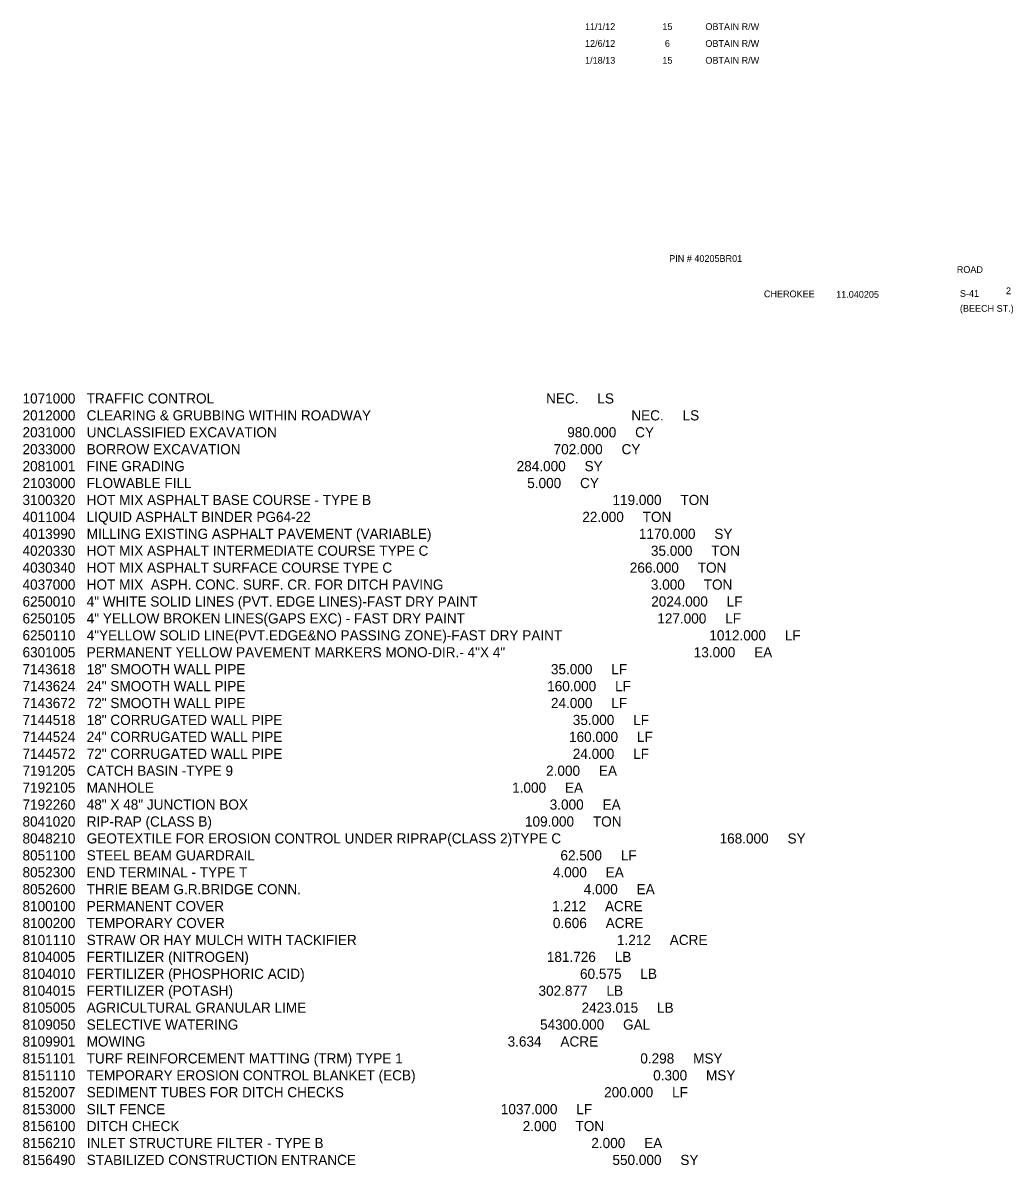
# Model space of a CAD drawing. Extents: x 160093 to 164626, y 177093 to 182727.
# Drawn here: x 163824 to 164555, y 178608 to 179452 of the extents above; entities that cross this region are included whole.
import ezdxf

# ---------------------------------------------------------------- set-up
doc = ezdxf.new("R2010")
doc.units = 0
for name, color, linetype in [('Default', 7, 'Continuous'), ('Level 37', 7, 'Continuous'), ('RD_SHT_TX', 7, 'Continuous')]:
    doc.layers.add(name, color=color, linetype=linetype)

msp = doc.modelspace()

# ---------------------------------------------------------------- texts
at = {"layer": 'Default'}
for s, height, p in [('ROAD', 5, (164513.57, 179266.9)), ('11.040205', 5, (164424.45, 179248.56)), ('S-41', 5, (164515.88, 179249.23)), ('(BEECH ST.)', 5, (164515.88, 179238.22)), ('1071000   TRAFFIC CONTROL                                                                                        NEC.     LS', 7.5, (163823.36, 179170.47)), ('2012000   CLEARING & GRUBBING WITHIN ROADWAY                                                                     NEC.     LS', 7.5, (163823.36, 179157.97)), ('2031000   UNCLASSIFIED EXCAVATION                                                                             980.000     CY', 7.5, (163823.36, 179145.47)), ('2033000   BORROW EXCAVATION                                                                                   702.000     CY', 7.5, (163823.36, 179132.97)), ('2081001   FINE GRADING                                                                                        284.000     SY', 7.5, (163823.36, 179120.47)), ('2103000   FLOWABLE FILL                                                                                         5.000     CY', 7.5, (163823.36, 179107.97)), ('3100320   HOT MIX ASPHALT BASE COURSE - TYPE B                                                                119.000     TON', 7.5, (163823.36, 179095.47)), ('4011004   LIQUID ASPHALT BINDER PG64-22                                                                        22.000     TON', 7.5, (163823.36, 179082.97)), ('4013990   MILLING EXISTING ASPHALT PAVEMENT (VARIABLE)                                                       1170.000     SY', 7.5, (163823.36, 179070.47)), ('4020330   HOT MIX ASPHALT INTERMEDIATE COURSE TYPE C                                                           35.000     TON', 7.5, (163823.36, 179057.97)), ('4030340   HOT MIX ASPHALT SURFACE COURSE TYPE C                                                               266.000     TON', 7.5, (163823.36, 179045.47)), ('4037000   HOT MIX  ASPH. CONC. SURF. CR. FOR DITCH PAVING                                                       3.000     TON', 7.5, (163823.36, 179032.97)), ('6250010   4" WHITE SOLID LINES (PVT. EDGE LINES)-FAST DRY PAINT                                              2024.000     LF', 7.5, (163823.36, 179020.47)), ('6250105   4" YELLOW BROKEN LINES(GAPS EXC) - FAST DRY PAINT                                                   127.000     LF', 7.5, (163823.36, 179007.97)), ('6250110   4"YELLOW SOLID LINE(PVT.EDGE&NO PASSING ZONE)-FAST DRY PAINT                                       1012.000     LF', 7.5, (163823.36, 178995.47)), ('6301005   PERMANENT YELLOW PAVEMENT MARKERS MONO-DIR.- 4"X 4"                                                  13.000     EA', 7.5, (163823.36, 178982.97)), ('7143618   18" SMOOTH WALL PIPE                                                                                 35.000     LF', 7.5, (163823.36, 178970.47)), ('7143624   24" SMOOTH WALL PIPE                                                                                160.000     LF', 7.5, (163823.36, 178957.97)), ('7143672   72" SMOOTH WALL PIPE                                                                                 24.000     LF', 7.5, (163823.36, 178945.47)), ('7144518   18" CORRUGATED WALL PIPE                                                                             35.000     LF', 7.5, (163823.36, 178932.97)), ('7144524   24" CORRUGATED WALL PIPE                                                                            160.000     LF', 7.5, (163823.36, 178920.47)), ('7144572   72" CORRUGATED WALL PIPE                                                                             24.000     LF', 7.5, (163823.36, 178907.97)), ('7191205   CATCH BASIN -TYPE 9                                                                                   2.000     EA', 7.5, (163823.36, 178895.47)), ('7192105   MANHOLE                                                                                               1.000     EA', 7.5, (163823.36, 178882.97)), ('7192260   48" X 48" JUNCTION BOX                                                                                3.000     EA', 7.5, (163823.36, 178870.47)), ('8041020   RIP-RAP (CLASS B)                                                                                   109.000     TON', 7.5, (163823.36, 178857.97)), ('8048210   GEOTEXTILE FOR EROSION CONTROL UNDER RIPRAP(CLASS 2)TYPE C                                          168.000     SY', 7.5, (163823.36, 178845.47)), ('8051100   STEEL BEAM GUARDRAIL                                                                                 62.500     LF', 7.5, (163823.36, 178832.97)), ('8052300   END TERMINAL - TYPE T                                                                                 4.000     EA', 7.5, (163823.36, 178820.47)), ('8052600   THRIE BEAM G.R.BRIDGE CONN.                                                                           4.000     EA', 7.5, (163823.36, 178807.97)), ('8100100   PERMANENT COVER                                                                                       1.212     ACRE', 7.5, (163823.36, 178795.47)), ('8100200   TEMPORARY COVER                                                                                       0.606     ACRE', 7.5, (163823.36, 178782.97)), ('8101110   STRAW OR HAY MULCH WITH TACKIFIER                                                                     1.212     ACRE', 7.5, (163823.36, 178770.47)), ('8104005   FERTILIZER (NITROGEN)                                                                               181.726     LB', 7.5, (163823.36, 178757.97)), ('8104010   FERTILIZER (PHOSPHORIC ACID)                                                                         60.575     LB', 7.5, (163823.36, 178745.47)), ('8104015   FERTILIZER (POTASH)                                                                                 302.877     LB', 7.5, (163823.36, 178732.97)), ('8105005   AGRICULTURAL GRANULAR LIME                                                                         2423.015     LB', 7.5, (163823.36, 178720.47)), ('8109050   SELECTIVE WATERING                                                                                54300.000     GAL', 7.5, (163823.36, 178707.97)), ('8109901   MOWING                                                                                                3.634     ACRE', 7.5, (163823.36, 178695.47)), ('8151101   TURF REINFORCEMENT MATTING (TRM) TYPE 1                                                               0.298     MSY', 7.5, (163823.36, 178682.97)), ('8151110   TEMPORARY EROSION CONTROL BLANKET (ECB)                                                               0.300     MSY', 7.5, (163823.36, 178670.47)), ('8152007   SEDIMENT TUBES FOR DITCH CHECKS                                                                     200.000     LF', 7.5, (163823.36, 178657.97)), ('8153000   SILT FENCE                                                                                         1037.000     LF', 7.5, (163823.36, 178645.47)), ('8156100   DITCH CHECK                                                                                           2.000     TON', 7.5, (163823.36, 178632.97)), ('8156210   INLET STRUCTURE FILTER - TYPE B                                                                       2.000     EA', 7.5, (163823.36, 178620.47)), ('8156490   STABILIZED CONSTRUCTION ENTRANCE                                                                    550.000     SY', 7.5, (163823.36, 178607.97))]:
    msp.add_text(s, height=height, dxfattribs=at).set_placement(p)
at = {"layer": 'Level 37'}
for s, p in [('PIN # 40205BR01', (164301.11, 179275.07)), ('CHEROKEE', (164371.1, 179248.93)), ('2', (164549.91, 179251.2))]:
    msp.add_text(s, height=5, dxfattribs=at).set_placement(p)
at = {"layer": 'RD_SHT_TX'}
for s, p in [('11/1/12', (164238.91, 179446.38)), ('15', (164296.1, 179446.38)), ('OBTAIN R/W', (164327.84, 179446.38)), ('12/6/12', (164238.91, 179433.91)), ('6', (164297.91, 179433.91)), ('OBTAIN R/W', (164327.84, 179433.91)), ('1/18/13', (164238.95, 179421.45)), ('15', (164296.1, 179421.45)), ('OBTAIN R/W', (164327.84, 179421.45))]:
    msp.add_text(s, height=5, dxfattribs=at).set_placement(p)

doc.saveas('drawing.dxf')
